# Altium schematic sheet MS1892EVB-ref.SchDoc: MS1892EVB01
size A3; Date: 2019-04-29; Author: Wang QB; Revision: V1.0.0; SheetNumber: 1; SheetTotal: 1; PageSetup: Record=PageOptions¦CenterHorizontal=True¦CenterVertical=True¦PrintScale=1.00¦XCorrection=1.00¦YCorrection=1.00¦PrintKind=0¦BorderSize=5000000¦LeftOffset=0¦BottomOffset=0¦Orientation=2¦PaperLength=1000¦PaperWidth=1000¦Scale=100¦PaperSource=7¦PrintQuality=-3¦MediaType=1¦DitherType=10¦PrintScaleMode=1¦PaperKind=A4¦PaperIndex=9
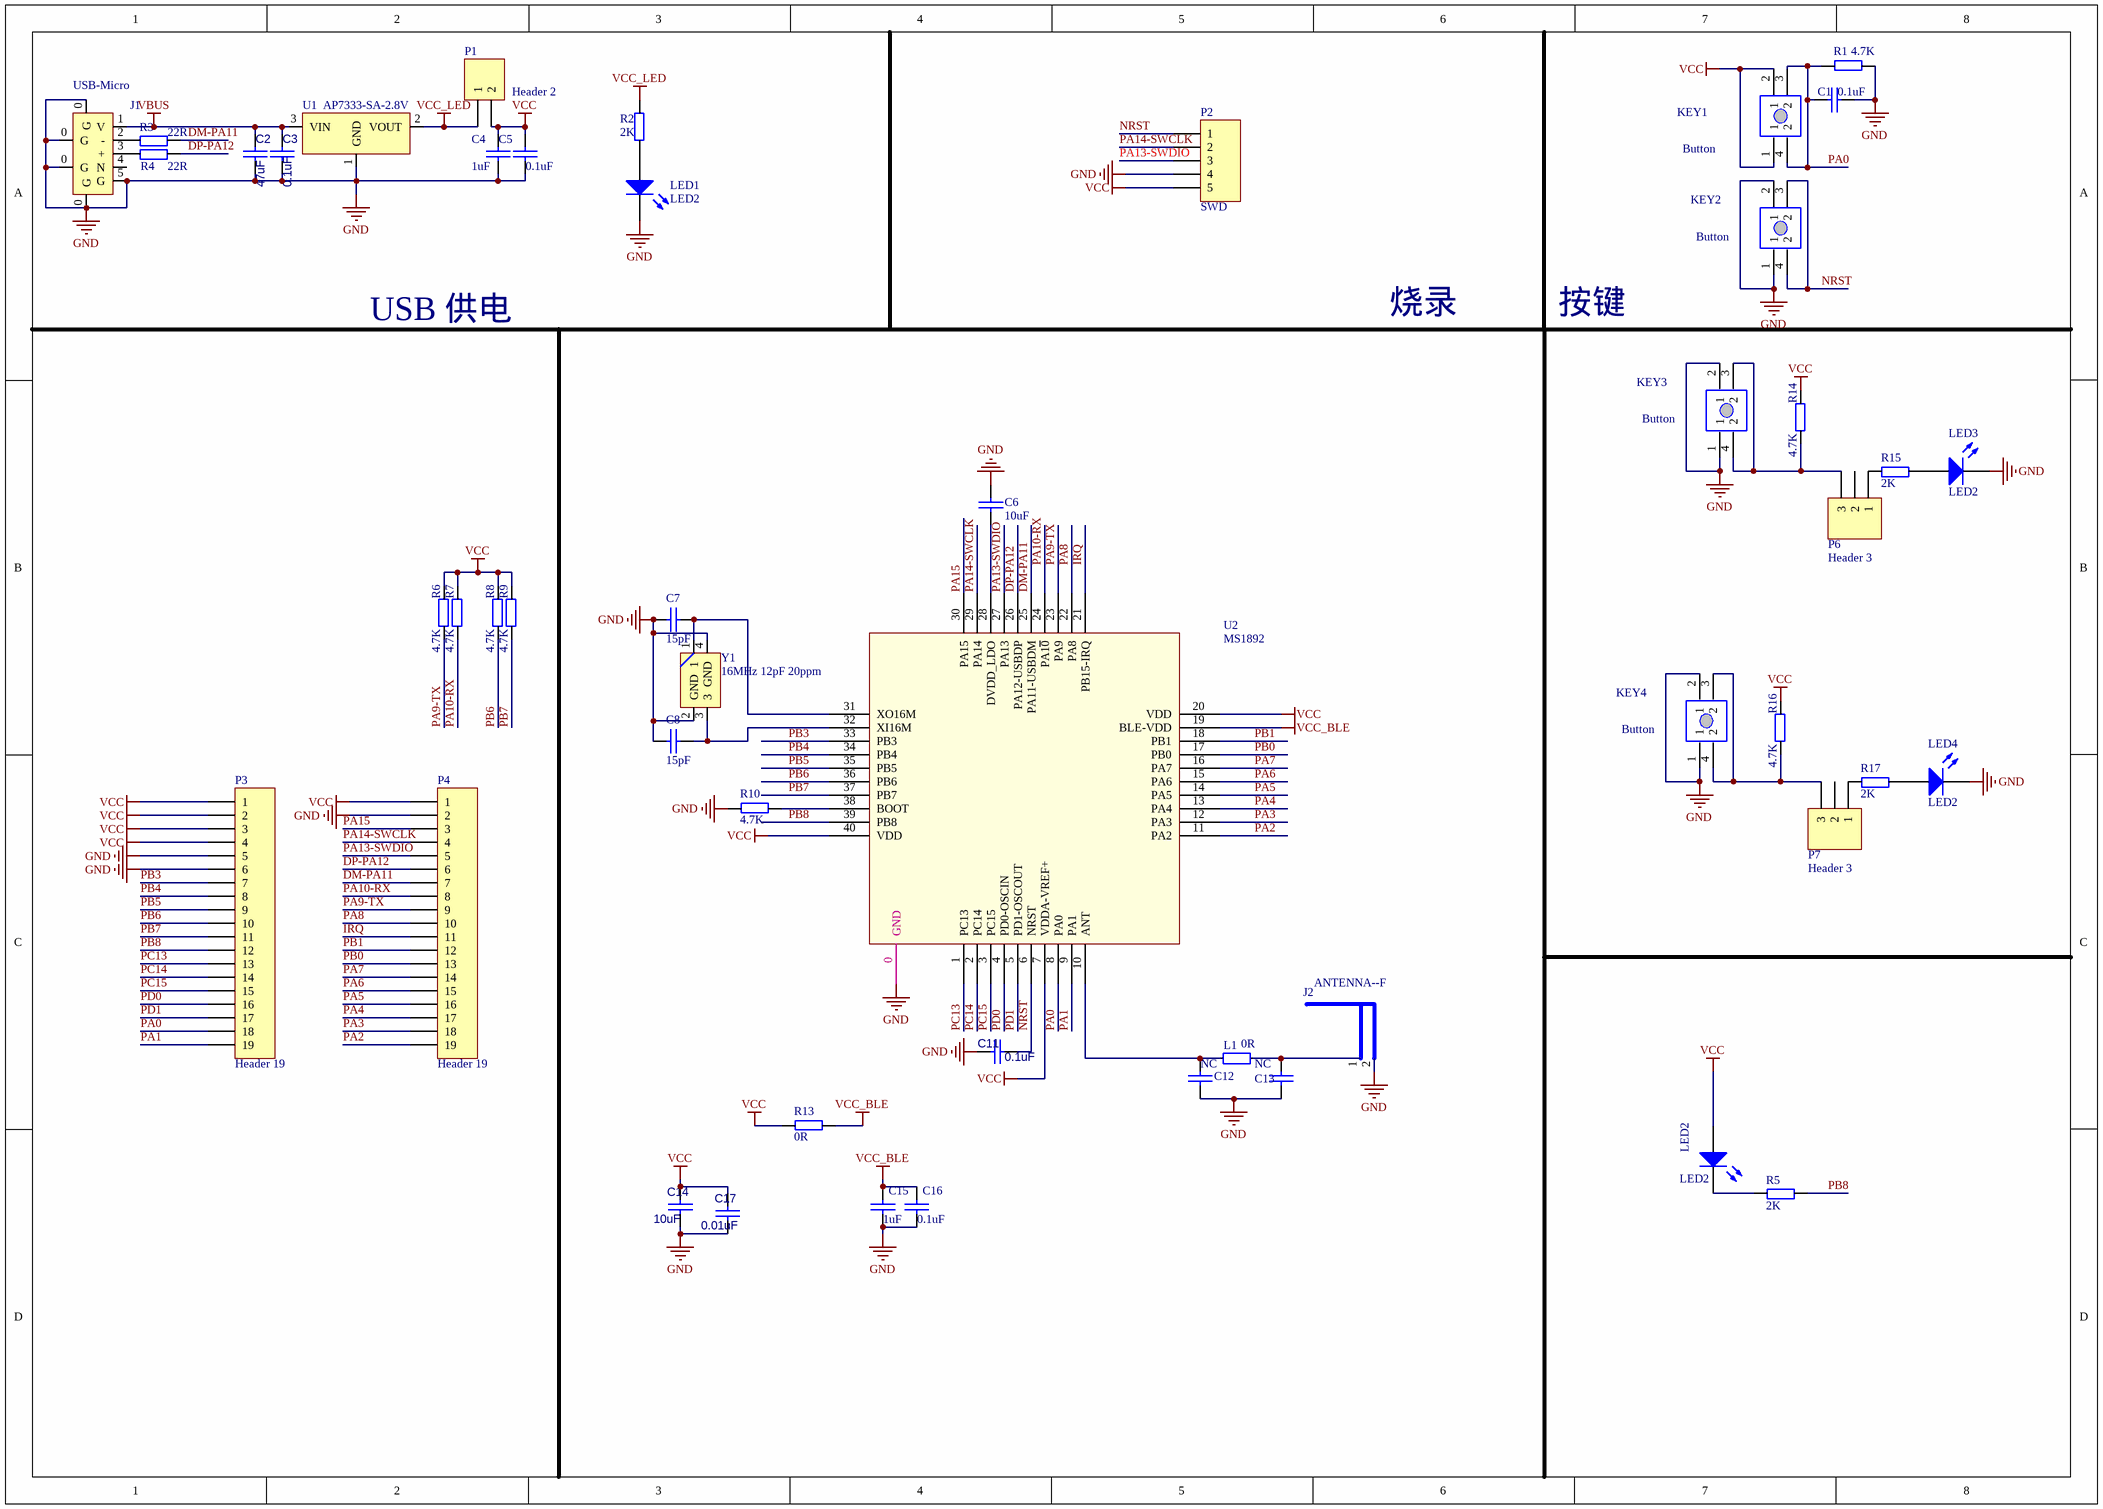
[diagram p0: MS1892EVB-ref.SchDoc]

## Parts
C1  0.1uF  [C0402]
C2  47uF  [c0603]
C3  0.1uF  [c0603]
C4  1uF  [C0603]
C5  0.1uF  [C0402]
C6  10uF  [C0402]
C7  15pF  [C0402]
C8  15pF  [C0402]
C11  0.1uF  [C0402]
C12  NC  [C0402]
C13  NC  [C0402]
C14  10uF  [C0402]
C15  1uF  [C0402]
C16  0.1uF  [C0402]
C17  0.01uF  [C0402]
J1  USB-Micro  [USB-MICRO]
J2  ANTENNA--F  [ANT-2]
KEY1  Button  [SW_DIP]
KEY2  Button  [SW_DIP]
KEY3  Button  [SW_DIP]
KEY4  Button  [SW_DIP]
L1  0R  [R0402]
LED1  LED2  [LED_0603]
LED2  LED2  [LED_0603]
LED3  LED2  [LED_0603]
LED4  LED2  [LED_0603]
P1  Header 2  [HDR1X2]
P2  SWD  [HDR1X5]
P3  Header 19  [HDR1X19]
P4  Header 19  [HDR1X19]
P6  Header 3  [HDR1X3]
P7  Header 3  [HDR1X3]
R1  4.7K  [R0402]
R2  2K  [R0402]
R3  22R  [R0402]
R4  22R  [R0402]
R5  2K  [R0402]
R6  4.7K  [R0402]
R7  4.7K  [R0402]
R8  4.7K  [R0402]
R9  4.7K  [R0402]
R10  4.7K  [R0402]
R13  0R  [R0402]
R14  4.7K  [R0402]
R15  2K  [R0402]
R16  4.7K  [R0402]
R17  2K  [R0402]
U1  AP7333-SA-2.8V  [SOT23_L]
U2  MS1892  [QFN-40_5x5x04P]
Y1  16MHz 12pF 20ppm  [XT3225]

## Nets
GND: C1.2 C2.2 C3.2 C4.2 C5.2 C6.1 C7.2 C8.2 C11.2 C12.2 C13.2 C14.2 C15.2 C16.2 C17.2 J1.0(G) J1.5(G) J2.2 KEY2.1 KEY2.2(1) KEY3.1 KEY3.2(1) KEY4.1 KEY4.2(1) LED1.2(K) LED3.2(K) LED4.2(K) P2.4 P3.5 P3.6 P4.2 R1.1 R10.2 U1.1(GND) U2.0(GND) Y1.2(GND) Y1.4(GND)
VBUS: C2.1 C3.1 J1.1(V) U1.3(VIN)
VCC: C4.1 C5.1 C14.1 C17.1 KEY1.1 KEY1.2(1) LED2.1(A) P1.2 P2.5 P3.1 P3.2 P3.3 P3.4 P4.1 R6.1 R7.1 R8.1 R9.1 R13.2 R14.1 R16.1 U2.7(VDDA-VREF+) U2.20(VDD) U2.40(VDD)
VCC_BLE: C15.1 C16.1 R13.1 U2.19(BLE-VDD)
VCC_LED: P1.1 R2.1 U1.2(VOUT)
DM-PA11: P4.7 R3.2 U2.25(PA11-USBDM)
DP-PA12: P4.6 R4.2 U2.26(PA12-USBDP)
IRQ: P4.11 U2.21(PB15-IRQ)
NRST: C11.1 KEY2.3(2) KEY2.4(2) P2.1 U2.6(NRST)
PA0: C1.1 KEY1.3(2) KEY1.4(2) P3.18 R1.2 U2.8(PA0)
PA1: P3.19 U2.9(PA1)
PA2: P4.19 U2.11(PA2)
PA3: P4.18 U2.12(PA3)
PA4: P4.17 U2.13(PA4)
PA5: P4.16 U2.14(PA5)
PA6: P4.15 U2.15(PA6)
PA7: P4.14 U2.16(PA7)
PA8: P4.10 U2.22(PA8)
PA9-TX: P4.9 R6.2 U2.23(PA9)
PA10-RX: P4.8 R7.2 U2.24(PA1~{0})
PA13-SWDIO: P2.3 P4.5 U2.27(PA13)
PA14-SWCLK: P2.2 P4.4 U2.29(PA14)
PA15: P4.3 U2.30(PA15)
PB0: P4.13 U2.17(PB0)
PB1: P4.12 U2.18(PB1)
PB3: P3.7 U2.33(PB3)
PB4: P3.8 U2.34(PB4)
PB5: P3.9 U2.35(PB5)
PB6: P3.10 R8.2 U2.36(PB6)
PB7: P3.11 R9.2 U2.37(PB7)
PB8: P3.12 R5.2 U2.39(PB8)
PC13: P3.13 U2.1(PC13)
PC14: P3.14 U2.2(PC14)
PC15: P3.15 U2.3(PC15)
PD0: P3.16 U2.4(PD0-OSCIN)
PD1: P3.17 U2.5(PD1-OSCOUT)
NetC6_2: C6.2 U2.28(DVDD_LDO)
NetC7_1: C7.1 U2.31(XO16M) Y1.1
NetC8_1: C8.1 U2.32(XI16M) Y1.3
NetC12_1: C12.1 L1.2 U2.10(ANT)
NetC13_1: C13.1 J2.1 L1.1
NetJ1_2: J1.2(-) R3.1
NetJ1_3: J1.3(+) R4.1
NetKEY3_3: KEY3.3(2) KEY3.4(2) P6.3 R14.2
NetKEY4_3: KEY4.3(2) KEY4.4(2) P7.3 R16.2
NetLED1_1: LED1.1(A) R2.2
NetLED2_2: LED2.2(K) R5.1
NetLED3_1: LED3.1(A) R15.2
NetLED4_1: LED4.1(A) R17.2
NetP6_1: P6.1 R15.1
NetP7_1: P7.1 R17.1
NetR10_1: R10.1 U2.38(BOOT)

Not connected (* = marked no-connect by the designer): J1 4(N); P6 2; P7 2

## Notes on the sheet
- 烧录
- 按键
- USB 供电

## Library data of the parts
C1-C8 C11-C17 = CAP: Capacitor
J2 = ANT
KEY1-KEY4 = KEY-4: PCB DECAL: KEY; value: AUTO
L1 = Res2: Resistor
LED1-LED4 = LED2: Typical RED, GREEN, YELLOW, AMBER GaAs LED
P1 = Header 2: Header, 2-Pin
P2 = Header 5: Header, 5-Pin
P3 P4 = Header 19: Header, 19-Pin
P6 P7 = Header 3: Header, 3-Pin
R1-R10 R13-R17 = R
U1 = SGM2300
U2 = MS1892: M3+MG126
Y1 = XTAL3225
